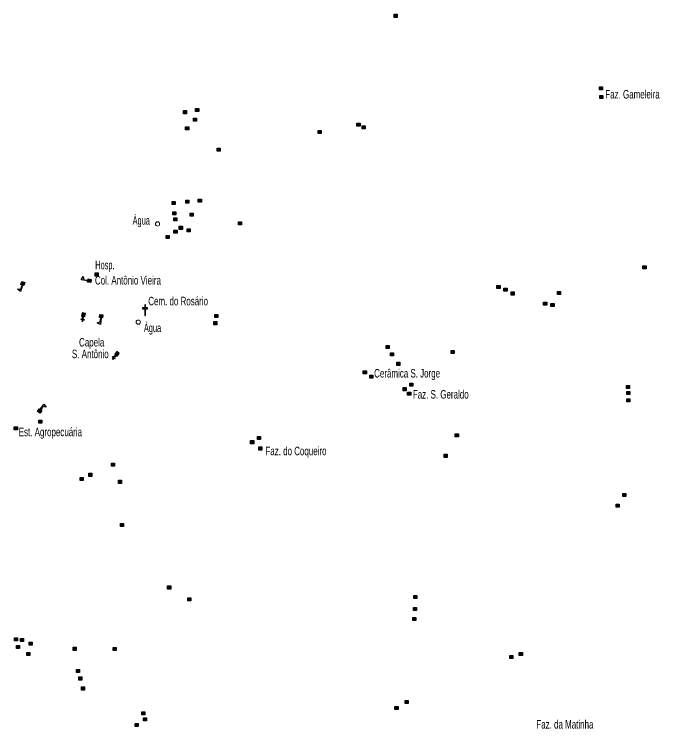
# Model space of a CAD drawing. Extents: x 447.8 to 473.9, y 7733.1 to 7760.8.
# Drawn here: x 454.9 to 460.97, y 7733.15 to 7739.87 of the extents above; entities that cross this region are included whole.
import ezdxf
from ezdxf.enums import TextEntityAlignment as Align

# ---------------------------------------------------------------- set-up
doc = ezdxf.new("R2010")
doc.units = 0
doc.header["$LTSCALE"] = 0.032
for name, color, linetype, lineweight in [('2', 7, 'Continuous', 25), ('20', 7, 'Continuous', 25), ('38', 7, 'Continuous', 13), ('4', 7, 'Continuous', 25), ('6', 7, 'Continuous', 25)]:
    doc.layers.add(name, color=color, linetype=linetype, lineweight=lineweight)
doc.layers.add('61', color=7, linetype='Continuous')

msp = doc.modelspace()

# ---------------------------------------------------------------- hatches: boundary and pattern name
at = {"layer": '2'}
for points in [[(458.4759, 7739.8672), (458.5049, 7739.8672), (458.5049, 7739.8382), (458.4759, 7739.8382)], [(460.4054, 7739.1851), (460.4344, 7739.1851), (460.4344, 7739.1561), (460.4054, 7739.1561)], [(460.4099, 7739.1027), (460.4389, 7739.1027), (460.4389, 7739.0737), (460.4099, 7739.0737)], [(456.6082, 7738.9814), (456.6372, 7738.9814), (456.6372, 7738.9524), (456.6082, 7738.9524)], [(456.4937, 7738.9608), (456.5227, 7738.9608), (456.5227, 7738.9318), (456.4937, 7738.9318)], [(456.5876, 7738.8899), (456.6166, 7738.8899), (456.6166, 7738.8609), (456.5876, 7738.8609)], [(458.1257, 7738.8441), (458.1547, 7738.8441), (458.1547, 7738.8151), (458.1257, 7738.8151)], [(456.5143, 7738.8097), (456.5433, 7738.8097), (456.5433, 7738.7807), (456.5143, 7738.7807)], [(457.7595, 7738.7754), (457.7885, 7738.7754), (457.7885, 7738.7464), (457.7595, 7738.7464)], [(458.1737, 7738.8189), (458.2027, 7738.8189), (458.2027, 7738.7899), (458.1737, 7738.7899)], [(456.8096, 7738.6083), (456.8386, 7738.6083), (456.8386, 7738.5793), (456.8096, 7738.5793)], [(456.3884, 7738.1071), (456.4174, 7738.1071), (456.4174, 7738.0781), (456.3884, 7738.0781)], [(456.5166, 7738.1185), (456.5456, 7738.1185), (456.5456, 7738.0895), (456.5166, 7738.0895)], [(456.6333, 7738.1277), (456.6623, 7738.1277), (456.6623, 7738.0987), (456.6333, 7738.0987)], [(456.393, 7738.0086), (456.422, 7738.0086), (456.422, 7737.9796), (456.393, 7737.9796)], [(456.5555, 7737.9972), (456.5845, 7737.9972), (456.5845, 7737.9682), (456.5555, 7737.9682)], [(456.4022, 7737.9537), (456.4312, 7737.9537), (456.4312, 7737.9247), (456.4022, 7737.9247)], [(457.011, 7737.9148), (457.04, 7737.9148), (457.04, 7737.8858), (457.011, 7737.8858)], [(456.4045, 7737.837), (456.4335, 7737.837), (456.4335, 7737.808), (456.4045, 7737.808)], [(456.4548, 7737.8736), (456.4838, 7737.8736), (456.4838, 7737.8446), (456.4548, 7737.8446)], [(456.528, 7737.8507), (456.557, 7737.8507), (456.557, 7737.8217), (456.528, 7737.8217)], [(456.3312, 7737.7866), (456.3602, 7737.7866), (456.3602, 7737.7576), (456.3312, 7737.7576)], [(460.8151, 7737.5028), (460.8441, 7737.5028), (460.8441, 7737.4738), (460.8151, 7737.4738)], [(455.6629, 7737.4341), (455.6919, 7737.4341), (455.6919, 7737.4051), (455.6629, 7737.4051)], [(459.4418, 7737.3174), (459.4708, 7737.3174), (459.4708, 7737.2884), (459.4418, 7737.2884)], [(459.5081, 7737.2922), (459.5371, 7737.2922), (459.5371, 7737.2632), (459.5081, 7737.2632)], [(459.5745, 7737.2556), (459.6035, 7737.2556), (459.6035, 7737.2266), (459.5745, 7737.2266)], [(460.0117, 7737.2602), (460.0407, 7737.2602), (460.0407, 7737.2312), (460.0117, 7737.2312)], [(459.8812, 7737.1595), (459.9102, 7737.1595), (459.9102, 7737.1305), (459.8812, 7737.1305)], [(459.9499, 7737.148), (459.9789, 7737.148), (459.9789, 7737.119), (459.9499, 7737.119)], [(456.789, 7737.045), (456.818, 7737.045), (456.818, 7737.016), (456.789, 7737.016)], [(456.7798, 7736.9764), (456.8088, 7736.9764), (456.8088, 7736.9474), (456.7798, 7736.9474)], [(458.4003, 7736.7521), (458.4293, 7736.7521), (458.4293, 7736.7231), (458.4003, 7736.7231)], [(459.0115, 7736.7063), (459.0405, 7736.7063), (459.0405, 7736.6773), (459.0115, 7736.6773)], [(458.4415, 7736.6834), (458.4705, 7736.6834), (458.4705, 7736.6544), (458.4415, 7736.6544)], [(458.501, 7736.5941), (458.53, 7736.5941), (458.53, 7736.5651), (458.501, 7736.5651)], [(458.1852, 7736.514), (458.2142, 7736.514), (458.2142, 7736.485), (458.1852, 7736.485)], [(458.247, 7736.4728), (458.276, 7736.4728), (458.276, 7736.4438), (458.247, 7736.4438)], [(458.5606, 7736.3561), (458.5896, 7736.3561), (458.5896, 7736.3271), (458.5606, 7736.3271)], [(458.6224, 7736.3973), (458.6514, 7736.3973), (458.6514, 7736.3683), (458.6224, 7736.3683)], [(460.6594, 7736.3767), (460.6884, 7736.3767), (460.6884, 7736.3477), (460.6594, 7736.3477)], [(458.6018, 7736.3126), (458.6308, 7736.3126), (458.6308, 7736.2836), (458.6018, 7736.2836)], [(460.664, 7736.3195), (460.693, 7736.3195), (460.693, 7736.2905), (460.664, 7736.2905)], [(460.664, 7736.2508), (460.693, 7736.2508), (460.693, 7736.2218), (460.664, 7736.2218)], [(455.1341, 7736.0494), (455.1631, 7736.0494), (455.1631, 7736.0204), (455.1341, 7736.0204)], [(454.903, 7735.9876), (454.932, 7735.9876), (454.932, 7735.9586), (454.903, 7735.9586)], [(457.1895, 7735.896), (457.2185, 7735.896), (457.2185, 7735.867), (457.1895, 7735.867)], [(459.0504, 7735.9212), (459.0794, 7735.9212), (459.0794, 7735.8922), (459.0504, 7735.8922)], [(457.1254, 7735.8571), (457.1544, 7735.8571), (457.1544, 7735.8281), (457.1254, 7735.8281)], [(457.2033, 7735.7976), (457.2323, 7735.7976), (457.2323, 7735.7686), (457.2033, 7735.7686)], [(458.9451, 7735.7289), (458.9741, 7735.7289), (458.9741, 7735.6999), (458.9451, 7735.6999)], [(455.8162, 7735.6465), (455.8452, 7735.6465), (455.8452, 7735.6175), (455.8162, 7735.6175)], [(455.6034, 7735.5504), (455.6324, 7735.5504), (455.6324, 7735.5214), (455.6034, 7735.5214)], [(455.5232, 7735.5115), (455.5522, 7735.5115), (455.5522, 7735.4825), (455.5232, 7735.4825)], [(455.8826, 7735.484), (455.9116, 7735.484), (455.9116, 7735.455), (455.8826, 7735.455)], [(460.6251, 7735.3604), (460.6541, 7735.3604), (460.6541, 7735.3314), (460.6251, 7735.3314)], [(460.562, 7735.2594), (460.591, 7735.2594), (460.591, 7735.2304), (460.562, 7735.2304)], [(455.9009, 7735.0789), (455.9299, 7735.0789), (455.9299, 7735.0499), (455.9009, 7735.0499)], [(456.3449, 7734.4907), (456.3739, 7734.4907), (456.3739, 7734.4617), (456.3449, 7734.4617)], [(456.5349, 7734.3785), (456.5639, 7734.3785), (456.5639, 7734.3495), (456.5349, 7734.3495)], [(458.659, 7734.4014), (458.688, 7734.4014), (458.688, 7734.3724), (458.659, 7734.3724)], [(458.6567, 7734.2893), (458.6857, 7734.2893), (458.6857, 7734.2603), (458.6567, 7734.2603)], [(458.6498, 7734.1931), (458.6788, 7734.1931), (458.6788, 7734.1641), (458.6498, 7734.1641)], [(454.9053, 7734.0032), (454.9343, 7734.0032), (454.9343, 7733.9742), (454.9053, 7733.9742)], [(454.9602, 7733.9963), (454.9892, 7733.9963), (454.9892, 7733.9673), (454.9602, 7733.9673)], [(455.0426, 7733.962), (455.0716, 7733.962), (455.0716, 7733.933), (455.0426, 7733.933)], [(454.9236, 7733.9299), (454.9526, 7733.9299), (454.9526, 7733.9009), (454.9236, 7733.9009)], [(455.4569, 7733.9139), (455.4859, 7733.9139), (455.4859, 7733.8849), (455.4569, 7733.8849)], [(455.8322, 7733.9116), (455.8612, 7733.9116), (455.8612, 7733.8826), (455.8322, 7733.8826)], [(455.0197, 7733.8658), (455.0487, 7733.8658), (455.0487, 7733.8368), (455.0197, 7733.8368)], [(459.5631, 7733.8361), (459.5921, 7733.8361), (459.5921, 7733.8071), (459.5631, 7733.8071)], [(459.6523, 7733.8658), (459.6813, 7733.8658), (459.6813, 7733.8368), (459.6523, 7733.8368)], [(455.4866, 7733.7056), (455.5156, 7733.7056), (455.5156, 7733.6766), (455.4866, 7733.6766)], [(455.5095, 7733.6346), (455.5385, 7733.6346), (455.5385, 7733.6056), (455.5095, 7733.6056)], [(455.5347, 7733.5408), (455.5637, 7733.5408), (455.5637, 7733.5118), (455.5347, 7733.5118)], [(458.5789, 7733.4126), (458.6079, 7733.4126), (458.6079, 7733.3836), (458.5789, 7733.3836)], [(458.4827, 7733.3577), (458.5117, 7733.3577), (458.5117, 7733.3287), (458.4827, 7733.3287)], [(456.1023, 7733.3073), (456.1313, 7733.3073), (456.1313, 7733.2783), (456.1023, 7733.2783)], [(456.0382, 7733.1975), (456.0672, 7733.1975), (456.0672, 7733.1685), (456.0382, 7733.1685)], [(456.1183, 7733.2501), (456.1473, 7733.2501), (456.1473, 7733.2211), (456.1183, 7733.2211)]]:
    msp.add_hatch(color=256, dxfattribs=at).paths.add_polyline_path(points)
at = {"layer": '4'}
for points in [[(455.6224, 7737.344), (455.5927, 7737.348), (455.5967, 7737.3777), (455.6264, 7737.3737)], [(455.0018, 7737.3437), (454.9927, 7737.3151), (454.9641, 7737.3242), (454.9732, 7737.3528)], [(455.7363, 7737.0411), (455.7332, 7737.0113), (455.7034, 7737.0143), (455.7064, 7737.0442)], [(455.1209, 7736.1302), (455.1369, 7736.1556), (455.1623, 7736.1396), (455.1463, 7736.1142)]]:
    msp.add_hatch(color=256, dxfattribs=at).paths.add_polyline_path(points)
at = {"layer": '6'}
for points in [[(455.566, 7737.0237), (455.5712, 7737.0532), (455.5417, 7737.0584), (455.5364, 7737.0289)], [(455.5487, 7737.0267), (455.5537, 7737.0258), (455.5489, 7736.9988), (455.5612, 7736.9966), (455.5603, 7736.9917), (455.548, 7736.9938), (455.545, 7736.9766), (455.54, 7736.9775), (455.5431, 7736.9947), (455.5308, 7736.9969), (455.5316, 7737.0018), (455.544, 7736.9996)], [(455.8705, 7736.6526), (455.8895, 7736.6758), (455.8663, 7736.6948), (455.8473, 7736.6716)], [(455.8569, 7736.6637), (455.8608, 7736.6605), (455.8433, 7736.6393), (455.853, 7736.6313), (455.8498, 7736.6275), (455.8402, 7736.6354), (455.8291, 7736.6219), (455.8252, 7736.625), (455.8363, 7736.6386), (455.8266, 7736.6465), (455.8298, 7736.6504), (455.8395, 7736.6424)]]:
    msp.add_hatch(color=256, dxfattribs=at).paths.add_polyline_path(points)

# ---------------------------------------------------------------- linework, layer by layer
at = {"layer": '2'}
for points in [[(458.4759, 7739.8672), (458.5049, 7739.8672), (458.5049, 7739.8382), (458.4759, 7739.8382)], [(460.4054, 7739.1851), (460.4344, 7739.1851), (460.4344, 7739.1561), (460.4054, 7739.1561)], [(460.4099, 7739.1027), (460.4389, 7739.1027), (460.4389, 7739.0737), (460.4099, 7739.0737)], [(456.6082, 7738.9814), (456.6372, 7738.9814), (456.6372, 7738.9524), (456.6082, 7738.9524)], [(456.4937, 7738.9608), (456.5227, 7738.9608), (456.5227, 7738.9318), (456.4937, 7738.9318)], [(456.5876, 7738.8899), (456.6166, 7738.8899), (456.6166, 7738.8609), (456.5876, 7738.8609)], [(458.1257, 7738.8441), (458.1547, 7738.8441), (458.1547, 7738.8151), (458.1257, 7738.8151)], [(456.5143, 7738.8097), (456.5433, 7738.8097), (456.5433, 7738.7807), (456.5143, 7738.7807)], [(457.7595, 7738.7754), (457.7885, 7738.7754), (457.7885, 7738.7464), (457.7595, 7738.7464)], [(458.1737, 7738.8189), (458.2027, 7738.8189), (458.2027, 7738.7899), (458.1737, 7738.7899)], [(456.8096, 7738.6083), (456.8386, 7738.6083), (456.8386, 7738.5793), (456.8096, 7738.5793)], [(456.3884, 7738.1071), (456.4174, 7738.1071), (456.4174, 7738.0781), (456.3884, 7738.0781)], [(456.5166, 7738.1185), (456.5456, 7738.1185), (456.5456, 7738.0895), (456.5166, 7738.0895)], [(456.6333, 7738.1277), (456.6623, 7738.1277), (456.6623, 7738.0987), (456.6333, 7738.0987)], [(456.393, 7738.0086), (456.422, 7738.0086), (456.422, 7737.9796), (456.393, 7737.9796)], [(456.5555, 7737.9972), (456.5845, 7737.9972), (456.5845, 7737.9682), (456.5555, 7737.9682)], [(456.4022, 7737.9537), (456.4312, 7737.9537), (456.4312, 7737.9247), (456.4022, 7737.9247)], [(457.011, 7737.9148), (457.04, 7737.9148), (457.04, 7737.8858), (457.011, 7737.8858)], [(456.4045, 7737.837), (456.4335, 7737.837), (456.4335, 7737.808), (456.4045, 7737.808)], [(456.4548, 7737.8736), (456.4838, 7737.8736), (456.4838, 7737.8446), (456.4548, 7737.8446)], [(456.528, 7737.8507), (456.557, 7737.8507), (456.557, 7737.8217), (456.528, 7737.8217)], [(456.3312, 7737.7866), (456.3602, 7737.7866), (456.3602, 7737.7576), (456.3312, 7737.7576)], [(460.8151, 7737.5028), (460.8441, 7737.5028), (460.8441, 7737.4738), (460.8151, 7737.4738)], [(455.6629, 7737.4341), (455.6919, 7737.4341), (455.6919, 7737.4051), (455.6629, 7737.4051)], [(459.4418, 7737.3174), (459.4708, 7737.3174), (459.4708, 7737.2884), (459.4418, 7737.2884)], [(459.5081, 7737.2922), (459.5371, 7737.2922), (459.5371, 7737.2632), (459.5081, 7737.2632)], [(459.5745, 7737.2556), (459.6035, 7737.2556), (459.6035, 7737.2266), (459.5745, 7737.2266)], [(460.0117, 7737.2602), (460.0407, 7737.2602), (460.0407, 7737.2312), (460.0117, 7737.2312)], [(459.8812, 7737.1595), (459.9102, 7737.1595), (459.9102, 7737.1305), (459.8812, 7737.1305)], [(459.9499, 7737.148), (459.9789, 7737.148), (459.9789, 7737.119), (459.9499, 7737.119)], [(456.789, 7737.045), (456.818, 7737.045), (456.818, 7737.016), (456.789, 7737.016)], [(456.7798, 7736.9764), (456.8088, 7736.9764), (456.8088, 7736.9474), (456.7798, 7736.9474)], [(458.4003, 7736.7521), (458.4293, 7736.7521), (458.4293, 7736.7231), (458.4003, 7736.7231)], [(459.0115, 7736.7063), (459.0405, 7736.7063), (459.0405, 7736.6773), (459.0115, 7736.6773)], [(458.4415, 7736.6834), (458.4705, 7736.6834), (458.4705, 7736.6544), (458.4415, 7736.6544)], [(458.501, 7736.5941), (458.53, 7736.5941), (458.53, 7736.5651), (458.501, 7736.5651)], [(458.1852, 7736.514), (458.2142, 7736.514), (458.2142, 7736.485), (458.1852, 7736.485)], [(458.247, 7736.4728), (458.276, 7736.4728), (458.276, 7736.4438), (458.247, 7736.4438)], [(458.5606, 7736.3561), (458.5896, 7736.3561), (458.5896, 7736.3271), (458.5606, 7736.3271)], [(458.6224, 7736.3973), (458.6514, 7736.3973), (458.6514, 7736.3683), (458.6224, 7736.3683)], [(460.6594, 7736.3767), (460.6884, 7736.3767), (460.6884, 7736.3477), (460.6594, 7736.3477)], [(458.6018, 7736.3126), (458.6308, 7736.3126), (458.6308, 7736.2836), (458.6018, 7736.2836)], [(460.664, 7736.3195), (460.693, 7736.3195), (460.693, 7736.2905), (460.664, 7736.2905)], [(460.664, 7736.2508), (460.693, 7736.2508), (460.693, 7736.2218), (460.664, 7736.2218)], [(455.1341, 7736.0494), (455.1631, 7736.0494), (455.1631, 7736.0204), (455.1341, 7736.0204)], [(454.903, 7735.9876), (454.932, 7735.9876), (454.932, 7735.9586), (454.903, 7735.9586)], [(457.1895, 7735.896), (457.2185, 7735.896), (457.2185, 7735.867), (457.1895, 7735.867)], [(459.0504, 7735.9212), (459.0794, 7735.9212), (459.0794, 7735.8922), (459.0504, 7735.8922)], [(457.1254, 7735.8571), (457.1544, 7735.8571), (457.1544, 7735.8281), (457.1254, 7735.8281)], [(457.2033, 7735.7976), (457.2323, 7735.7976), (457.2323, 7735.7686), (457.2033, 7735.7686)], [(458.9451, 7735.7289), (458.9741, 7735.7289), (458.9741, 7735.6999), (458.9451, 7735.6999)], [(455.8162, 7735.6465), (455.8452, 7735.6465), (455.8452, 7735.6175), (455.8162, 7735.6175)], [(455.6034, 7735.5504), (455.6324, 7735.5504), (455.6324, 7735.5214), (455.6034, 7735.5214)], [(455.5232, 7735.5115), (455.5522, 7735.5115), (455.5522, 7735.4825), (455.5232, 7735.4825)], [(455.8826, 7735.484), (455.9116, 7735.484), (455.9116, 7735.455), (455.8826, 7735.455)], [(460.6251, 7735.3604), (460.6541, 7735.3604), (460.6541, 7735.3314), (460.6251, 7735.3314)], [(460.562, 7735.2594), (460.591, 7735.2594), (460.591, 7735.2304), (460.562, 7735.2304)], [(455.9009, 7735.0789), (455.9299, 7735.0789), (455.9299, 7735.0499), (455.9009, 7735.0499)], [(456.3449, 7734.4907), (456.3739, 7734.4907), (456.3739, 7734.4617), (456.3449, 7734.4617)], [(456.5349, 7734.3785), (456.5639, 7734.3785), (456.5639, 7734.3495), (456.5349, 7734.3495)], [(458.659, 7734.4014), (458.688, 7734.4014), (458.688, 7734.3724), (458.659, 7734.3724)], [(458.6567, 7734.2893), (458.6857, 7734.2893), (458.6857, 7734.2603), (458.6567, 7734.2603)], [(458.6498, 7734.1931), (458.6788, 7734.1931), (458.6788, 7734.1641), (458.6498, 7734.1641)], [(454.9053, 7734.0032), (454.9343, 7734.0032), (454.9343, 7733.9742), (454.9053, 7733.9742)], [(454.9602, 7733.9963), (454.9892, 7733.9963), (454.9892, 7733.9673), (454.9602, 7733.9673)], [(455.0426, 7733.962), (455.0716, 7733.962), (455.0716, 7733.933), (455.0426, 7733.933)], [(454.9236, 7733.9299), (454.9526, 7733.9299), (454.9526, 7733.9009), (454.9236, 7733.9009)], [(455.4569, 7733.9139), (455.4859, 7733.9139), (455.4859, 7733.8849), (455.4569, 7733.8849)], [(455.8322, 7733.9116), (455.8612, 7733.9116), (455.8612, 7733.8826), (455.8322, 7733.8826)], [(455.0197, 7733.8658), (455.0487, 7733.8658), (455.0487, 7733.8368), (455.0197, 7733.8368)], [(459.5631, 7733.8361), (459.5921, 7733.8361), (459.5921, 7733.8071), (459.5631, 7733.8071)], [(459.6523, 7733.8658), (459.6813, 7733.8658), (459.6813, 7733.8368), (459.6523, 7733.8368)], [(455.4866, 7733.7056), (455.5156, 7733.7056), (455.5156, 7733.6766), (455.4866, 7733.6766)], [(455.5095, 7733.6346), (455.5385, 7733.6346), (455.5385, 7733.6056), (455.5095, 7733.6056)], [(455.5347, 7733.5408), (455.5637, 7733.5408), (455.5637, 7733.5118), (455.5347, 7733.5118)], [(458.5789, 7733.4126), (458.6079, 7733.4126), (458.6079, 7733.3836), (458.5789, 7733.3836)], [(458.4827, 7733.3577), (458.5117, 7733.3577), (458.5117, 7733.3287), (458.4827, 7733.3287)], [(456.1023, 7733.3073), (456.1313, 7733.3073), (456.1313, 7733.2783), (456.1023, 7733.2783)], [(456.0382, 7733.1975), (456.0672, 7733.1975), (456.0672, 7733.1685), (456.0382, 7733.1685)], [(456.1183, 7733.2501), (456.1473, 7733.2501), (456.1473, 7733.2211), (456.1183, 7733.2211)]]:
    msp.add_lwpolyline(points, close=True, dxfattribs=at)
at = {"layer": '20'}
for points in [[(456.1291, 7737.1057), (456.1091, 7737.1057), (456.1091, 7737.0972), (456.1291, 7737.0972), (456.1291, 7737.0337)], [(456.1371, 7737.1057), (456.1371, 7737.1337), (456.1291, 7737.1337), (456.1291, 7737.1057)], [(456.1291, 7737.0337), (456.1371, 7737.0337), (456.1371, 7737.0972)], [(456.1371, 7737.0972), (456.1571, 7737.0972), (456.1571, 7737.1057), (456.1371, 7737.1057)]]:
    msp.add_lwpolyline(points, dxfattribs=at)
at = {"layer": '38'}
for centre in [(456.2501, 7737.8953), (456.0691, 7736.9718)]:
    msp.add_circle(centre, 0.02, dxfattribs=at)
at = {"layer": '4'}
for p, q in [((455.5944, 7737.3604), (455.595, 7737.3653)), ((454.9807, 7737.3189), (454.976, 7737.3204)), ((455.7208, 7737.0125), (455.7158, 7737.0131)), ((455.1475, 7736.1489), (455.1517, 7736.1463))]:
    msp.add_line(p, q, dxfattribs=at)
for points in [[(455.5944, 7737.3604), (455.5324, 7737.3687), (455.5495, 7737.4017), (455.5559, 7737.3706), (455.595, 7737.3653)], [(455.6224, 7737.344), (455.5927, 7737.348), (455.5967, 7737.3777), (455.6264, 7737.3737)], [(454.9807, 7737.3189), (454.9618, 7737.2593), (454.9322, 7737.2819), (454.964, 7737.2828), (454.976, 7737.3204)], [(455.0018, 7737.3437), (454.9927, 7737.3151), (454.9641, 7737.3242), (454.9732, 7737.3528)], [(455.7363, 7737.0411), (455.7332, 7737.0113), (455.7034, 7737.0143), (455.7064, 7737.0442)], [(455.7208, 7737.0125), (455.7144, 7736.9504), (455.6809, 7736.9664), (455.7118, 7736.9738), (455.7158, 7737.0131)], [(455.1209, 7736.1302), (455.1369, 7736.1556), (455.1623, 7736.1396), (455.1463, 7736.1142)], [(455.1475, 7736.1489), (455.1808, 7736.2018), (455.2038, 7736.1726), (455.1728, 7736.1797), (455.1517, 7736.1463)]]:
    msp.add_lwpolyline(points, close=True, dxfattribs=at)
at = {"layer": '6'}
for points in [[(455.566, 7737.0237), (455.5712, 7737.0532), (455.5417, 7737.0584), (455.5364, 7737.0289)], [(455.5487, 7737.0267), (455.5537, 7737.0258), (455.5489, 7736.9988), (455.5612, 7736.9966), (455.5603, 7736.9917), (455.548, 7736.9938), (455.545, 7736.9766), (455.54, 7736.9775), (455.5431, 7736.9947), (455.5308, 7736.9969), (455.5316, 7737.0018), (455.544, 7736.9996)], [(455.8705, 7736.6526), (455.8895, 7736.6758), (455.8663, 7736.6948), (455.8473, 7736.6716)], [(455.8569, 7736.6637), (455.8608, 7736.6605), (455.8433, 7736.6393), (455.853, 7736.6313), (455.8498, 7736.6275), (455.8402, 7736.6354), (455.8291, 7736.6219), (455.8252, 7736.625), (455.8363, 7736.6386), (455.8266, 7736.6465), (455.8298, 7736.6504), (455.8395, 7736.6424)]]:
    msp.add_lwpolyline(points, close=True, dxfattribs=at)

# ---------------------------------------------------------------- texts
at = {"layer": '61'}
for s, width, p in [('Faz. Gameleira', 0.7, (460.4607, 7739.0752)), ('Hosp.', 0.65, (455.664, 7737.4689)), ('Col. Antônio Vieira', 0.7, (455.6616, 7737.3253)), ('Cem. do Rosário', 0.7, (456.1629, 7737.1299)), ('Água', 0.65, (456.1216, 7736.8782)), ('Cerâmica S. Jorge', 0.7, (458.287, 7736.4509)), ('Faz. S. Geraldo', 0.7, (458.6514, 7736.2527)), ('Est. Agropecuária', 0.7, (454.9448, 7735.8987)), ('Faz. do Coqueiro', 0.7, (457.2647, 7735.7198)), ('Faz. da Matinha', 0.7, (459.8125, 7733.1489))]:
    msp.add_text(s, height=0.08, dxfattribs=dict(at, width=width)).set_placement(p)
for s, width, p in [('Água', 0.65, (456.1779, 7737.8886)), ('   Capela  ', 0.7, (455.7907, 7736.7427)), ('S. Antônio', 0.7, (455.7907, 7736.6327))]:
    msp.add_text(s, height=0.08, dxfattribs=dict(at, width=width)).set_placement(p, align=Align.RIGHT)

doc.saveas('drawing.dxf')
